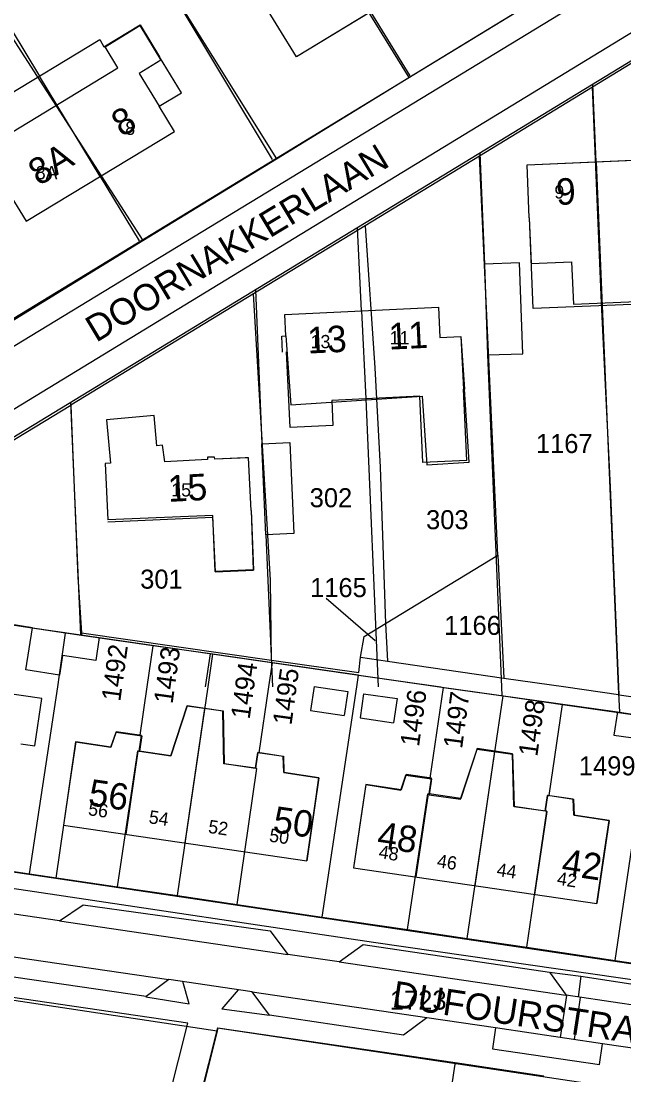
# Model space of a CAD drawing. Extents: x 148816 to 151297, y 399515 to 402500.
# Drawn here: x 149815.4 to 149872.3, y 400463.3 to 400562.9 of the extents above; entities that cross this region are included whole.
import ezdxf

# ---------------------------------------------------------------- set-up
doc = ezdxf.new("R2010")
doc.units = 0
for name, color, linetype in [('B01 Hoofdgebouw  [D] Norm', 7, 'Continuous'), ('B01 Hoofdgebouw  [T] Norm', 7, 'Continuous'), ('B01 hoofgebouw', 7, 'Continuous'), ('B02 Bijgebouw  [D] Norm', 7, 'Continuous'), ('B02 Bijgebouw  [T] Norm', 7, 'Continuous'), ('B07 Tussenmuur  [D] Norm', 7, 'Continuous'), ('G01 perceelsgrens', 7, 'Continuous'), ('T04 Haag heg  [D] Gem', 7, 'Continuous'), ('V00 Kant verharding algemeen  [T] Norm', 7, 'Continuous'), ('V00 Kant verharding algemeen secundair  [T] Gem', 7, 'Continuous'), ('Z01 perceelnummer', 7, 'Continuous'), ('Z02 huisnummer', 7, 'Continuous'), ('Z02 Huisnummer  [Tekst] Norm', 7, 'Continuous'), ('Z06 straatnaam', 7, 'Continuous')]:
    doc.layers.add(name, color=color, linetype=linetype)

msp = doc.modelspace()

# ---------------------------------------------------------------- linework, layer by layer
at = {"layer": 'B01 Hoofdgebouw  [D] Norm'}
for p, q in [((149823.225, 400560.5), (149826.636, 400562.569)), ((149826.636, 400562.569), (149828.48, 400559.53)), ((149806.945, 400551.551), (149822.821, 400561.167)), ((149822.821, 400561.167), (149823.225, 400560.5)), ((149869.68, 400549.62), (149870.265, 400536.025)), ((149863.754, 400535.745), (149863.385, 400544.34)), ((149877.985, 400536.359), (149863.754, 400535.745)), ((149847.55, 400535.55), (149847.952, 400527.219)), ((149840.816, 400524.509), (149840.47, 400531.668)), ((149853.042, 400527.465), (149844.733, 400527.063)), ((149853.345, 400521.203), (149853.042, 400527.465)), ((149857.497, 400521.404), (149857.17, 400528.13)), ((149844.733, 400527.063), (149844.847, 400524.704)), ((149844.847, 400524.704), (149840.816, 400524.509)), ((149857.497, 400521.404), (149853.345, 400521.203)), ((149837.11, 400516.66), (149837.34, 400511.044)), ((149823.588, 400515.598), (149833.48, 400516.046)), ((149833.48, 400516.046), (149833.714, 400510.88)), ((149833.714, 400510.88), (149837.34, 400511.044))]:
    msp.add_line(p, q, dxfattribs=at)
msp.add_lwpolyline([(149816.697, 400494.444), (149817.351, 400498.896), (149809.946, 400499.984), (149809.328, 400495.777)], dxfattribs=at)
at = {"layer": 'B01 Hoofdgebouw  [T] Norm'}
for p, q in [((149855.4, 400568.06), (149841.4, 400559.53)), ((149841.4, 400559.53), (149838.07, 400565)), ((149830.53, 400556.15), (149828.48, 400559.53)), ((149828.42, 400554.87), (149830.53, 400556.15)), ((149829.87, 400552.47), (149828.42, 400554.87)), ((149815.88, 400544), (149829.87, 400552.47)), ((149863.17, 400549.34), (149876.19, 400549.9)), ((149863.38, 400544.34), (149863.17, 400549.34)), ((149814.44, 400546.38), (149815.88, 400544)), ((149840.3, 400535.2), (149854.8, 400535.9)), ((149840.41, 400533.18), (149840.3, 400535.2)), ((149854.8, 400535.9), (149854.94, 400533.02)), ((149840.02, 400533.14), (149840.41, 400533.18)), ((149840.09, 400531.65), (149840.02, 400533.14)), ((149854.94, 400533.02), (149856.93, 400533.12)), ((149856.93, 400533.12), (149857.17, 400528.13)), ((149827.95, 400525.64), (149823.47, 400525.24)), ((149823.47, 400525.24), (149823.85, 400521.15)), ((149828.22, 400522.79), (149827.95, 400525.64)), ((149828.75, 400522.84), (149828.22, 400522.79)), ((149828.96, 400521.27), (149828.75, 400522.84)), ((149833, 400521.48), (149828.96, 400521.27)), ((149833.67, 400521.72), (149832.99, 400521.71)), ((149832.99, 400521.71), (149833, 400521.48)), ((149833.68, 400521.51), (149833.67, 400521.72)), ((149836.55, 400521.64), (149833.68, 400521.51)), ((149836.86, 400521.66), (149836.55, 400521.64)), ((149837.11, 400516.66), (149836.86, 400521.66)), ((149823.85, 400521.15), (149823.35, 400521.11)), ((149823.35, 400521.11), (149823.58, 400515.78)), ((149829.522, 400493.507), (149831.092, 400498.22)), ((149831.092, 400498.22), (149834.477, 400497.731)), ((149834.477, 400497.731), (149834.567, 400492.757)), ((149823.881, 400494.322), (149824.367, 400495.727)), ((149824.367, 400495.727), (149826.785, 400495.397)), ((149826.785, 400495.397), (149826.572, 400493.923)), ((149815.381, 400494.636), (149816.697, 400494.444)), ((149815.417, 400494.884), (149815.417, 400494.884)), ((149820.55, 400494.803), (149819.395, 400486.952)), ((149820.55, 400494.803), (149823.881, 400494.322)), ((149826.572, 400493.923), (149829.522, 400493.507)), ((149837.535, 400492.32), (149837.75, 400493.805)), ((149837.75, 400493.805), (149840.165, 400493.455)), ((149840.165, 400493.455), (149840.217, 400491.932)), ((149856.888, 400489.413), (149858.472, 400494.136)), ((149858.472, 400494.136), (149861.797, 400493.655)), ((149861.797, 400493.655), (149861.96, 400488.71)), ((149834.567, 400492.757), (149837.535, 400492.32)), ((149840.217, 400491.932), (149843.524, 400491.424)), ((149843.525, 400491.424), (149842.37, 400483.573)), ((149851.26, 400490.25), (149851.719, 400491.669)), ((149851.719, 400491.669), (149854.141, 400491.307)), ((149854.141, 400491.307), (149853.926, 400489.824)), ((149847.94, 400490.771), (149846.782, 400482.921)), ((149847.94, 400490.771), (149851.26, 400490.25)), ((149853.926, 400489.824), (149856.888, 400489.413)), ((149864.91, 400488.282), (149865.126, 400489.768)), ((149865.126, 400489.768), (149867.568, 400489.413)), ((149867.568, 400489.413), (149867.609, 400487.881)), ((149861.96, 400488.71), (149864.91, 400488.282)), ((149867.609, 400487.881), (149870.913, 400487.38)), ((149870.913, 400487.38), (149869.755, 400479.531)), ((149819.395, 400486.952), (149842.37, 400483.573)), ((149846.782, 400482.921), (149869.755, 400479.531))]:
    msp.add_line(p, q, dxfattribs=at)
at = {"layer": 'B01 hoofgebouw'}
for points in [[(149853.46, 400575.97), (149855.99, 400571.65), (149853.93, 400570.45), (149855.4, 400568.061), (149841.4, 400559.53), (149838.07, 400565.001), (149836.05, 400563.78), (149834.024, 400567.099)], [(149814.439, 400546.383), (149812.565, 400549.477), (149810.526, 400548.243), (149808.508, 400551.579), (149811.769, 400553.552), (149813.002, 400551.515), (149824.537, 400558.496), (149823.329, 400560.492), (149826.624, 400562.486), (149828.598, 400559.225), (149826.539, 400557.979), (149828.42, 400554.872)], [(149810.252, 400548.45), (149812.29, 400545.083), (149814.439, 400546.383), (149815.882, 400544), (149829.875, 400552.469), (149828.42, 400554.872), (149830.529, 400556.148), (149828.481, 400559.531)], [(149863.38, 400544.34), (149863.17, 400549.34), (149876.19, 400549.9), (149876.58, 400540.83), (149881.03, 400541.02), (149881.24, 400536.03)], [(149863.38, 400544.34), (149863.573, 400540.007), (149867.376, 400540.171), (149867.549, 400536.168), (149878, 400536.619), (149878.485, 400525.359), (149881.7, 400525.498), (149881.24, 400536.03)], [(149840.09, 400531.65), (149840.02, 400533.14), (149840.41, 400533.18), (149840.3, 400535.2), (149854.8, 400535.9), (149854.94, 400533.02), (149856.93, 400533.12), (149857.253, 400528.13)], [(149840.41, 400533.18), (149840.853, 400526.657), (149853.278, 400527.462), (149853.697, 400520.985), (149857.699, 400521.244), (149857.253, 400528.13)], [(149837.11, 400516.66), (149836.86, 400521.66), (149833.68, 400521.51), (149833.67, 400521.72), (149832.99, 400521.71), (149833, 400521.48), (149828.96, 400521.27), (149828.75, 400522.84), (149828.22, 400522.79), (149827.95, 400525.64), (149823.47, 400525.24), (149823.85, 400521.15), (149823.35, 400521.11), (149823.58, 400515.78)], [(149837.11, 400516.66), (149837.315, 400511.071), (149833.735, 400510.918), (149833.507, 400516.207), (149823.58, 400515.78)], [(149815.381, 400494.637), (149816.697, 400494.444), (149817.351, 400498.896), (149809.946, 400499.984), (149809.328, 400495.78)], [(149843.098, 400488.52), (149843.526, 400491.428), (149840.192, 400491.92), (149840.144, 400493.443), (149837.74, 400493.798), (149837.521, 400492.314), (149834.553, 400492.752), (149834.434, 400497.722), (149831.07, 400498.218), (149829.525, 400493.493), (149826.557, 400493.931), (149826.776, 400495.415), (149824.362, 400495.771), (149823.886, 400494.325), (149820.552, 400494.817), (149820.123, 400491.899)], [(149870.485, 400484.477), (149870.914, 400487.386), (149867.6, 400487.875), (149867.522, 400489.403), (149865.108, 400489.759), (149864.889, 400488.275), (149861.921, 400488.713), (149861.804, 400493.683), (149858.45, 400494.178), (149856.904, 400489.453), (149853.936, 400489.891), (149854.155, 400491.375), (149851.751, 400491.73), (149851.275, 400490.284), (149847.941, 400490.776), (149847.512, 400487.867)], [(149820.123, 400491.899), (149819.395, 400486.952), (149842.37, 400483.573), (149843.098, 400488.52)], [(149847.512, 400487.867), (149846.782, 400482.921), (149869.755, 400479.531), (149870.485, 400484.477)]]:
    msp.add_lwpolyline(points, dxfattribs=at)
at = {"layer": 'B02 Bijgebouw  [D] Norm'}
for points in [[(149859.14, 400539.946), (149859.444, 400531.37), (149862.771, 400531.488), (149862.467, 400540.064)], [(149840.778, 400523.085), (149841.162, 400514.498), (149838.52, 400514.38), (149838.136, 400522.967)]]:
    msp.add_lwpolyline(points, close=True, dxfattribs=at)
at = {"layer": 'B02 Bijgebouw  [T] Norm'}
for p, q in [((149843.074, 400500.05), (149842.739, 400497.775)), ((149843.074, 400500.05), (149846.239, 400499.584)), ((149846.239, 400499.584), (149845.904, 400497.309)), ((149847.742, 400499.363), (149847.408, 400497.088)), ((149847.742, 400499.363), (149850.908, 400498.897)), ((149850.908, 400498.897), (149850.574, 400496.622)), ((149842.739, 400497.775), (149845.904, 400497.309)), ((149871.697, 400497.636), (149871.376, 400495.46)), ((149871.697, 400497.636), (149877.969, 400496.71)), ((149847.408, 400497.088), (149850.574, 400496.622)), ((149871.376, 400495.46), (149877.648, 400494.534))]:
    msp.add_line(p, q, dxfattribs=at)
msp.add_lwpolyline([(149815.837, 400501.621), (149816.471, 400505.596), (149822.763, 400504.67), (149822.443, 400502.493), (149819.323, 400502.969), (149819.027, 400501.112)], close=True, dxfattribs=at)
at = {"layer": 'B07 Tussenmuur  [D] Norm'}
for p, q in [((149822.875, 400548.235), (149817.131, 400557.722)), ((149822.875, 400548.235), (149817.131, 400557.722)), ((149830.881, 400485.263), (149832.754, 400497.98)), ((149830.881, 400485.263), (149832.754, 400497.98)), ((149826.436, 400493.936), (149825.281, 400486.085)), ((149826.436, 400493.936), (149825.281, 400486.085)), ((149858.267, 400481.226), (149860.138, 400493.9)), ((149858.267, 400481.226), (149860.138, 400493.9)), ((149837.638, 400492.29), (149836.483, 400484.439)), ((149837.638, 400492.29), (149836.483, 400484.439)), ((149853.826, 400489.902), (149852.668, 400482.052)), ((149853.826, 400489.902), (149852.668, 400482.052)), ((149865.026, 400488.248), (149863.868, 400480.399)), ((149865.026, 400488.248), (149863.868, 400480.399))]:
    msp.add_line(p, q, dxfattribs=at)
at = {"layer": 'G01 perceelsgrens'}
for points in [[(149833.761, 400587.255), (149838.758, 400579.057), (149852.011, 400557.573)], [(149821.4, 400578.928), (149839.525, 400549.917)], [(149808.72, 400570.38), (149826.89, 400542.171)], [(149852.011, 400557.573), (149860.145, 400562.561), (149864.819, 400565.414)], [(149880.033, 400563.188), (149869.358, 400556.674)], [(149839.525, 400549.917), (149852.011, 400557.573)], [(149869.358, 400556.674), (149858.691, 400550.166)], [(149871.849, 400500), (149871.036, 400518.876), (149870.207, 400536.283), (149869.358, 400556.674)], [(149858.691, 400550.166), (149847.888, 400543.575)], [(149860.425, 400512.44), (149858.691, 400550.166)], [(149826.89, 400542.171), (149839.525, 400549.917)], [(149847.888, 400543.575), (149837.349, 400537.145)], [(149847.888, 400543.575), (149848.791, 400530.167), (149849.292, 400520.783), (149849.789, 400505.99)], [(149813.984, 400534.257), (149826.89, 400542.171)], [(149837.349, 400537.145), (149820.086, 400526.612)], [(149839.043, 400502.543), (149838.959, 400510.099), (149837.349, 400537.145)], [(149776.278, 400500), (149820.086, 400526.612)], [(149820.086, 400526.612), (149820.143, 400524.943), (149820.767, 400510.364), (149821.097, 400505.108)], [(149849.789, 400505.99), (149860.425, 400512.44)], [(149860.425, 400512.44), (149860.99, 400500.844)], [(149819.605, 400505.092), (149810.956, 400506.363)], [(149847.449, 400502.802), (149847.78, 400504.771), (149849.789, 400505.99)], [(149849.789, 400505.99), (149849.995, 400502.433)], [(149818.864, 400500), (149819.036, 400501.136), (149819.605, 400505.092)], [(149821.108, 400504.876), (149819.605, 400505.092)], [(149821.097, 400505.108), (149821.108, 400504.876)], [(149821.097, 400505.108), (149839.043, 400502.543)], [(149827.878, 400503.902), (149821.108, 400504.876)], [(149827.302, 400500), (149827.878, 400503.902)], [(149833.505, 400503.094), (149827.878, 400503.902)], [(149833.05, 400500), (149833.505, 400503.094)], [(149839.132, 400502.285), (149833.505, 400503.094)], [(149838.798, 400500), (149839.132, 400502.285)], [(149839.043, 400502.543), (149847.299, 400501.363)], [(149847.255, 400501.118), (149839.132, 400502.285)], [(149847.299, 400501.363), (149847.449, 400502.802)], [(149847.449, 400502.802), (149849.995, 400502.433)], [(149849.995, 400502.433), (149860.99, 400500.844)], [(149847.087, 400500), (149847.255, 400501.118)], [(149847.255, 400501.118), (149855.029, 400500)], [(149860.99, 400500.844), (149866.832, 400500)], [(149816.192, 400482.355), (149818.864, 400500)], [(149824.514, 400481.123), (149826.409, 400493.953), (149826.557, 400493.931), (149826.776, 400495.415), (149826.628, 400495.437), (149827.302, 400500)], [(149830.152, 400480.289), (149833.05, 400500)], [(149835.789, 400479.454), (149837.669, 400492.292), (149837.521, 400492.314), (149837.74, 400493.798), (149837.888, 400493.776), (149838.798, 400500)], [(149843.821, 400478.265), (149847.087, 400500)], [(149851.882, 400477.071), (149853.788, 400489.913), (149853.936, 400489.891), (149854.155, 400491.375), (149854.007, 400491.397), (149855.279, 400499.964)], [(149855.029, 400500), (149855.279, 400499.964)], [(149855.279, 400499.964), (149860.903, 400499.156)], [(149866.832, 400500), (149871.815, 400499.28)], [(149871.815, 400499.28), (149871.88, 400499.271)], [(149871.88, 400499.271), (149871.849, 400500)], [(149871.88, 400499.271), (149882.885, 400497.68)], [(149857.52, 400476.237), (149860.903, 400499.156)], [(149860.903, 400499.156), (149866.522, 400498.349)], [(149863.149, 400475.403), (149865.038, 400488.253), (149864.889, 400488.275), (149865.108, 400489.759), (149865.256, 400489.737), (149866.522, 400498.349)], [(149866.522, 400498.349), (149874.894, 400497.146)], [(149871.494, 400474.168), (149874.894, 400497.146)], [(149788.629, 400486.407), (149788.994, 400485.961), (149789.488, 400485.356), (149791.97, 400484.291), (149794.98, 400483.882), (149816.674, 400480.69), (149848.673, 400475.899), (149875.035, 400472.064), (149890.511, 400469.792), (149911.733, 400466.607), (149927.062, 400464.372), (149944.375, 400461.703), (149955.709, 400460.082)], [(149807.54, 400483.629), (149816.192, 400482.355)], [(149816.192, 400482.355), (149824.514, 400481.123)], [(149824.514, 400481.123), (149830.152, 400480.289)], [(149830.152, 400480.289), (149835.789, 400479.454)], [(149835.789, 400479.454), (149843.821, 400478.265)], [(149843.821, 400478.265), (149851.882, 400477.071)], [(149851.882, 400477.071), (149857.52, 400476.237)], [(149857.52, 400476.237), (149863.149, 400475.403)], [(149863.149, 400475.403), (149871.494, 400474.168)], [(149791.727, 400473.863), (149833.927, 400467.522)], [(149871.494, 400474.168), (149879.818, 400472.935)], [(149833.927, 400467.522), (149831.158, 400456.491)], [(149833.99, 400467.774), (149833.927, 400467.522)], [(149856.371, 400464.477), (149833.99, 400467.774)], [(149856.371, 400464.477), (149856.323, 400464.157)], [(149864.75, 400463.235), (149856.371, 400464.477)], [(149856.323, 400464.157), (149855.311, 400457.373), (149854.382, 400451.179)]]:
    msp.add_lwpolyline(points, dxfattribs=at)
at = {"layer": 'T04 Haag heg  [D] Gem'}
for p, q in [((149826.16, 400571.408), (149839.117, 400549.825)), ((149809.331, 400570.606), (149817.131, 400557.722)), ((149848.4, 400563.795), (149852.095, 400557.731)), ((149869.68, 400549.62), (149869.366, 400556.928)), ((149858.698, 400550.423), (149859.14, 400539.946)), ((149822.875, 400548.235), (149826.547, 400542.169)), ((149847.55, 400535.55), (149847.171, 400543.396)), ((149837.522, 400537.513), (149838.136, 400522.967)), ((149870.265, 400536.025), (149871.786, 400500)), ((149859.444, 400531.37), (149860.768, 400500)), ((149847.952, 400527.219), (149849.101, 400500)), ((149820.076, 400526.877), (149821.013, 400504.928)), ((149838.52, 400514.38), (149839.127, 400500)), ((149816.468, 400505.577), (149805.2, 400507.45)), ((149822.764, 400504.679), (149854.915, 400500)), ((149833.245, 400503.127), (149832.791, 400500)), ((149854.915, 400500), (149871.697, 400497.636)), ((149860.768, 400500), (149860.803, 400499.173)), ((149871.786, 400500), (149871.887, 400497.608))]:
    msp.add_line(p, q, dxfattribs=at)
at = {"layer": 'V00 Kant verharding algemeen  [T] Norm'}
msp.add_line((149783.531, 400504.6), (149905.805, 400579.215), dxfattribs=at)
for points in [[(149905.385, 400590.127), (149757.598, 400500)], [(149870.076, 400565.907), (149761.842, 400500)], [(149782.665, 400506.73), (149873.293, 400561.998)], [(149819.398, 400486.952), (149818.688, 400481.922)], [(149798.693, 400484.89), (149926.625, 400465.901), (149926.259, 400463.557)], [(149819.039, 400477.892), (149792.023, 400481.858)], [(149819.039, 400477.892), (149821.264, 400479.403), (149838.902, 400476.96), (149840.57, 400474.73)], [(149860.184, 400467.793), (149853.716, 400468.745), (149851.491, 400467.103), (149838.844, 400468.99), (149837.201, 400471.196), (149829.349, 400472.362), (149827.195, 400470.744), (149808.609, 400473.455), (149807.039, 400475.612), (149805.593, 400475.832)], [(149845.434, 400474.016), (149847.689, 400475.655), (149865.303, 400473.038), (149866.875, 400470.868)], [(149845.434, 400474.016), (149840.57, 400474.73)], [(149865.303, 400473.038), (149868.257, 400472.668), (149867.989, 400470.705)], [(149868.257, 400472.668), (149881.778, 400470.604)], [(149816.39, 400444.858), (149824.028, 400440.019), (149831.127, 400468.219), (149804.699, 400472.101), (149804.202, 400468.845), (149800.827, 400469.343), (149801.197, 400472.293)], [(149827.191, 400470.735), (149831.265, 400470.06), (149830.658, 400472.163)], [(149835.892, 400471.391), (149834.363, 400469.597), (149838.846, 400468.984)], [(149879.661, 400468.976), (149871.938, 400470.125), (149866.875, 400470.868)], [(149833.931, 400467.803), (149826.307, 400437.475)], [(149833.931, 400467.803), (149939.981, 400451.934), (149950.016, 400450.288)], [(149860.184, 400467.793), (149859.914, 400465.805), (149870.005, 400464.316), (149870.298, 400466.288), (149860.184, 400467.793)], [(149878.316, 400465.119), (149870.298, 400466.288)]]:
    msp.add_lwpolyline(points, dxfattribs=at)
at = {"layer": 'V00 Kant verharding algemeen secundair  [T] Gem'}
for p, q in [((149819.039, 400477.892), (149840.568, 400474.732)), ((149807.039, 400475.612), (149829.349, 400472.363)), ((149845.434, 400474.016), (149866.816, 400470.872)), ((149837.201, 400471.204), (149853.715, 400468.754))]:
    msp.add_line(p, q, dxfattribs=at)
for points in [[(149866.34, 400466.882), (149866.94, 400470.859)], [(149868.197, 400470.674), (149867.608, 400466.7)]]:
    msp.add_lwpolyline(points, dxfattribs=at)
at = {"layer": 'Z01 perceelnummer'}
msp.add_lwpolyline([(149844.206, 400508.392), (149848.825, 400504.405)], dxfattribs=at)

# ---------------------------------------------------------------- texts
for s, p in [('1167', (149864.004, 400522.101)), ('302', (149842.647, 400516.982)), ('303', (149853.634, 400514.906)), ('301', (149826.643, 400509.289)), ('1165', (149842.686, 400508.492)), ('1166', (149855.343, 400504.921)), ('1499', (149868.058, 400491.648)), ('1723', (149850.218, 400469.515))]:
    msp.add_text(s, height=1.8, dxfattribs=at).set_placement(p)
for s, rotation, p in [('1492', 82.15454, (149824.759, 400498.581)), ('1493', 82.16239, (149829.698, 400498.35)), ('1494', 82.05653, (149836.972, 400496.894)), ('1495', 82.18022, (149840.924, 400496.336)), ('1496', 82.04859, (149852.961, 400494.304)), ('1497', 82.35191, (149857.031, 400494.113)), ('1498', 82.1151, (149864.133, 400493.366))]:
    msp.add_text(s, height=1.8, rotation=rotation, dxfattribs=at).set_placement(p)
at = {"layer": 'Z02 huisnummer'}
for s, rotation, p in [('8', 31.20949, (149824.921, 400551.901)), ('8A', 31.20949, (149817.078, 400547.295)), ('9', 2.46466, (149865.956, 400545.536)), ('13', 2.75083, (149842.477, 400531.5)), ('11', 2.75083, (149850.15, 400531.87)), ('15', 2.97967, (149829.315, 400517.485)), ('56', 351.65913, (149821.655, 400488.843)), ('50', 351.65913, (149839.082, 400486.28)), ('48', 351.60243, (149848.924, 400484.828)), ('42', 351.60243, (149866.342, 400482.258))]:
    msp.add_text(s, height=2.5, rotation=rotation, dxfattribs=at).set_placement(p)
at = {"layer": 'Z02 Huisnummer  [Tekst] Norm'}
for s, p in [('8', (149825.236, 400552.17)), ('8A', (149816.788, 400547.973)), ('9', (149865.75, 400546.15)), ('13', (149842.74, 400532.01)), ('11', (149850.2, 400532.37)), ('15', (149829.58, 400518))]:
    msp.add_text(s, height=1.25, dxfattribs=at).set_placement(p)
for s, p in [('56', (149821.675, 400487.9)), ('54', (149827.398, 400487.134)), ('52', (149833.007, 400486.227)), ('50', (149838.766, 400485.404)), ('48', (149849.109, 400483.832)), ('46', (149854.608, 400482.978)), ('44', (149860.242, 400482.152)), ('42', (149865.942, 400481.318))]:
    msp.add_text(s, height=1.25, rotation=351.45658, dxfattribs=at).set_placement(p)
at = {"layer": 'Z06 straatnaam'}
for s, rotation, p in [('DOORNAKKERLAAN', 31.05216, (149822.487, 400532.507)), ('DUFOURSTRAAT', 351.37577, (149850.332, 400469.778))]:
    msp.add_text(s, height=2.5, rotation=rotation, dxfattribs=at).set_placement(p)

doc.saveas('drawing.dxf')
